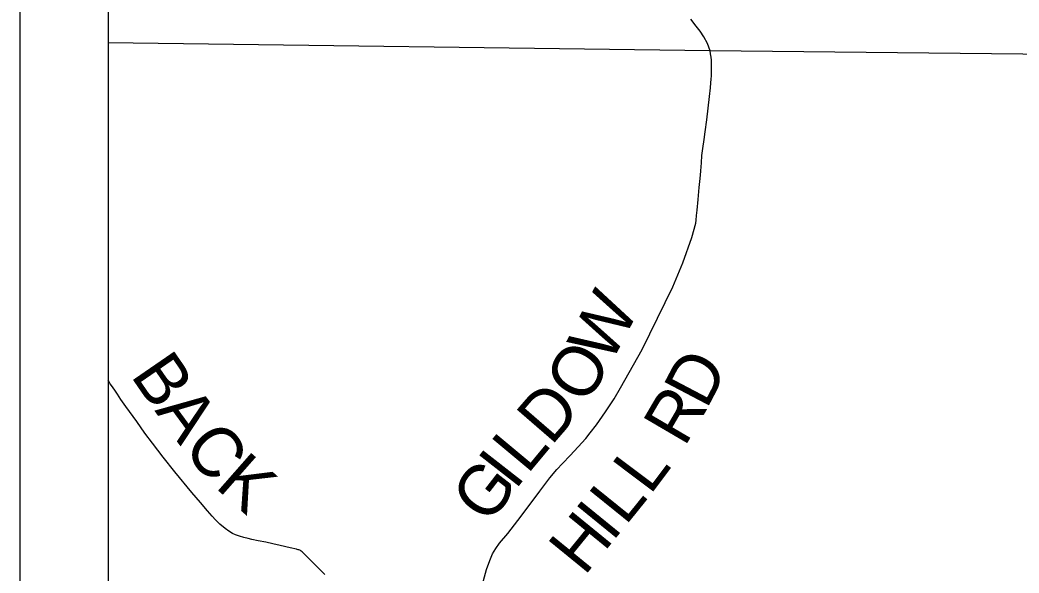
# Model space of a CAD drawing. Extents: x -10 to 158, y 8 to 33.
# Drawn here: x 126.004 to 127.137, y 29.785 to 30.412 of the extents above; entities that cross this region are included whole.
import ezdxf

# ---------------------------------------------------------------- set-up
doc = ezdxf.new("R2010")
doc.units = 0
for name, color, linetype in [('GM_X_Township_Road', 7, 'Continuous'), ('GM_X_Township_Road_Text', 7, 'Continuous'), ('GM_X_Township_Text', 7, 'Continuous'), ('SH_Data', 7, 'Continuous')]:
    doc.layers.add(name, color=color, linetype=linetype)

msp = doc.modelspace()

# ---------------------------------------------------------------- linework, layer by layer
at = {"layer": 'GM_X_Township_Road'}
for points in [[(126.7865, 30.377), (126.7836, 30.3853), (126.7795, 30.3931), (126.7752, 30.3993), (126.7709, 30.4051), (126.7649, 30.4129)], [(126.5201, 29.7416), (126.5331, 29.789), (126.5369, 29.7993), (126.5398, 29.8065), (126.5436, 29.8127), (126.5478, 29.8189), (126.5572, 29.8297), (126.5723, 29.8493), (126.5935, 29.8777), (126.6049, 29.8928), (126.6128, 29.9025), (126.619, 29.909), (126.6278, 29.9183), (126.6368, 29.928), (126.6457, 29.9376), (126.6507, 29.9439), (126.6576, 29.9529), (126.6681, 29.9679), (126.6776, 29.9826), (126.6851, 29.995), (126.7094, 30.0386), (126.7442, 30.1094), (126.7556, 30.1366), (126.766, 30.1654), (126.7703, 30.1817), (126.7707, 30.1851), (126.7713, 30.1905), (126.772, 30.1963), (126.773, 30.2086), (126.7743, 30.2221), (126.7751, 30.2288), (126.7757, 30.2362), (126.776, 30.2411), (126.7767, 30.2503), (126.7773, 30.2583), (126.7781, 30.2638), (126.7784, 30.2663), (126.7797, 30.2767), (126.7809, 30.2853), (126.7828, 30.2988), (126.7858, 30.3254), (126.7869, 30.3352), (126.7875, 30.341), (126.7878, 30.3449), (126.788, 30.3489), (126.7881, 30.3536), (126.7882, 30.3586), (126.7881, 30.3643), (126.788, 30.3666), (126.7877, 30.37), (126.7872, 30.3736), (126.7865, 30.377)], [(126.3495, 29.7832), (126.3341, 29.7986), (126.3248, 29.808), (126.3238, 29.8089), (126.3228, 29.8098), (126.3219, 29.8104), (126.3211, 29.8108), (126.3203, 29.8111), (126.3194, 29.8114), (126.3184, 29.8116), (126.3174, 29.8119), (126.3104, 29.8135), (126.299, 29.8163), (126.2905, 29.8182), (126.2826, 29.8198), (126.2741, 29.8216), (126.2668, 29.8231), (126.2626, 29.8241), (126.2577, 29.8253), (126.253, 29.8267), (126.2483, 29.8283), (126.2449, 29.8299), (126.2406, 29.8324), (126.2366, 29.8353), (126.2305, 29.8405), (126.2257, 29.8454), (126.2219, 29.8495), (126.2165, 29.8555), (126.2085, 29.865), (126.1989, 29.8764), (126.1795, 29.8998), (126.1663, 29.9162), (126.1541, 29.932), (126.1456, 29.9434), (126.1362, 29.9566), (126.124, 29.9737), (126.1183, 29.9818), (126.1143, 29.9879), (126.1122, 29.991), (126.1087, 29.9961), (126.1063, 29.9996), (126.1038, 30.0035)]]:
    msp.add_lwpolyline(points, dxfattribs=at)
at = {"layer": 'GM_X_Township_Text'}
for points in [[(130.4564, 28.3588), (130.4692, 29.1401), (130.4693, 29.1486), (130.4806, 29.8369), (130.4806, 29.8379), (130.4865, 31.8623), (126.1038, 31.8623), (126.1038, 30.3865)], [(126.1038, 30.3865), (126.7862, 30.3776), (127.3186, 30.3717), (127.3748, 30.3712), (127.3749, 29.9155), (127.3818, 29.8865), (127.391, 29.7447), (127.3932, 29.6834), (127.3898, 29.6674), (127.3806, 29.6412), (127.3727, 29.3597), (127.4764, 29.3589), (128.0062, 29.36), (128.408, 29.3517), (128.4072, 28.9327), (128.4042, 28.3758), (128.6622, 28.3709), (128.9974, 28.365), (129.3242, 28.3598), (129.7479, 28.3639), (130.1791, 28.3585), (130.4564, 28.3588), (130.461, 27.8534), (130.5863, 27.8482)], [(126.1038, 30.3865), (126.1038, 27.0364), (126.3333, 27.0308), (126.5452, 27.0287), (127.0949, 27.0121), (127.9467, 26.9899), (128.0604, 26.987), (128.3868, 26.9847), (128.4032, 28.3535), (128.4042, 28.3758)]]:
    msp.add_lwpolyline(points, dxfattribs=at)
at = {"layer": 'SH_Data'}
for p, q in [((126.0038, 31.9623), (126.0038, 24.9623)), ((126.1038, 31.8623), (126.1038, 25.0623))]:
    msp.add_line(p, q, dxfattribs=at)

# ---------------------------------------------------------------- texts
at = {"layer": 'GM_X_Township_Road_Text'}
for s, rotation, p in [('W', 62.4239, (126.6735, 30.0205)), ('O', 58.1517, (126.6449, 29.974)), ('B', 304.5377, (126.1285, 30.0091)), ('D', 62.2872, (126.7824, 29.9695)), ('D', 49.1043, (126.6063, 29.9283)), ('R', 59.6788, (126.7575, 29.9268)), ('A', 306.3158, (126.1561, 29.9691)), ('C', 308.7513, (126.1873, 29.9267)), ('L', 50.2136, (126.5793, 29.8959)), ('K', 318.6656, (126.2239, 29.8825)), ('I', 52.0216, (126.5653, 29.8779)), ('L', 53.0507, (126.7184, 29.8724)), ('G', 52.2209, (126.5347, 29.8384)), ('L', 51.1093, (126.6905, 29.8377)), ('I', 50.8636, (126.6756, 29.8194)), ('H', 50.8003, (126.6439, 29.7806))]:
    msp.add_text(s, height=0.0568, rotation=rotation, dxfattribs=at).set_placement(p)

doc.saveas('drawing.dxf')
